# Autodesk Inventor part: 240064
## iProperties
Created: 2006-10
Part Number: 240064
Material: FSt
Description: Spannstift
Vendor: Autodesk Inc.
Document SubType Name: Modeling
Standard: ISO 8752
Designer: I.Baliuc
Standards Organization: ISO
Language: de-DE
Size Designation: 5 x 28  A
Categories: <MemberInstance Version="R10.0.0"><Categories><Category DisplayName="Schrauben" InternalName="e4da775c-781d-43d5-af7c-5136215cf5a6" Mnemonic="FSTN"><Category Di
Density: 7.85 g/cm^3
Abmessung: 5 x 28 A
Author: T.Messerschmitt
Comments: ISO 8752 - 5 x 28 A
Revision Number: 240064
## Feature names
1. Körper [Revolution]
2. Schnitt [Extrusion]
